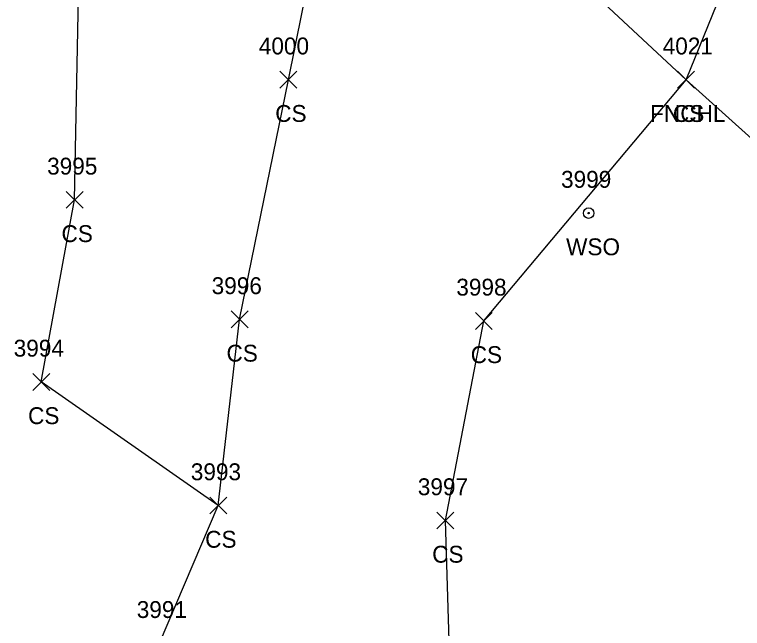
# Model space of a CAD drawing. Extents: x 49137 to 50946, y 9590 to 10709.
# Drawn here: x 49899.3 to 49985.5, y 10501.9 to 10574.6 of the extents above; entities that cross this region are included whole.
import ezdxf

# ---------------------------------------------------------------- set-up
doc = ezdxf.new("R2010")
doc.units = 0
for name, color, linetype in [('L_A', 7, 'Continuous'), ('L_I', 7, 'Continuous'), ('L_TIC', 7, 'Continuous'), ('LELB', 7, 'Continuous'), ('LFNC', 7, 'Continuous'), ('U_A', 7, 'Continuous'), ('U_I', 7, 'Continuous'), ('UWV', 7, 'Continuous')]:
    doc.layers.add(name, color=color, linetype=linetype)

msp = doc.modelspace()

# ---------------------------------------------------------------- linework, layer by layer
at = {"layer": 'L_TIC'}
for points in [[(49930.688, 10565.921), (49932.688, 10567.921)], [(49932.688, 10565.921), (49930.688, 10567.921)], [(49977.784, 10565.915), (49979.784, 10567.915)], [(49979.784, 10565.915), (49977.784, 10567.915)], [(49977.784, 10565.915), (49979.784, 10567.915)], [(49979.784, 10565.915), (49977.784, 10567.915)], [(49905.375, 10551.679), (49907.375, 10553.679)], [(49907.375, 10551.679), (49905.375, 10553.679)], [(49924.914, 10537.511), (49926.914, 10539.511)], [(49926.914, 10537.511), (49924.914, 10539.511)], [(49953.835, 10537.337), (49955.835, 10539.337)], [(49955.835, 10537.337), (49953.835, 10539.337)], [(49901.416, 10530.105), (49903.416, 10532.105)], [(49903.416, 10530.105), (49901.416, 10532.105)], [(49922.39, 10515.456), (49924.39, 10517.456)], [(49924.39, 10515.456), (49922.39, 10517.456)], [(49922.39, 10515.456), (49924.39, 10517.456)], [(49924.39, 10515.456), (49922.39, 10517.456)], [(49949.273, 10513.682), (49951.273, 10515.682)], [(49951.273, 10513.682), (49949.273, 10515.682)]]:
    msp.add_lwpolyline(points, dxfattribs=at)
at = {"layer": 'LELB'}
for points in [[(49923.39, 10516.456), (49902.416, 10531.105), (49906.375, 10552.679), (49907.277, 10598.859), (49920.121, 10622.736)], [(49949.012, 10468.446), (49916.195, 10486.119), (49916.422, 10500.13), (49923.39, 10516.456), (49925.914, 10538.511), (49931.688, 10566.921), (49939.033, 10603.327)], [(49951.21, 10484.843), (49950.273, 10514.682), (49954.835, 10538.337), (49978.784, 10566.915), (49984.016, 10579.774), (50007.672, 10594.029), (50036.301, 10599.804)]]:
    msp.add_lwpolyline(points, dxfattribs=at)
at = {"layer": 'LFNC'}
msp.add_lwpolyline([(49920.121, 10622.736), (49939.033, 10603.327), (49958.78, 10585.587), (49978.784, 10566.915), (49996.681, 10550.816)], dxfattribs=at)
at = {"layer": 'UWV'}
for radius in [0.625, 0.0833]:
    msp.add_circle((49967.242, 10551.116), radius, dxfattribs=at)

# ---------------------------------------------------------------- texts
at = {"layer": 'L_A'}
for s, p in [('CS', (49930.129, 10561.921)), ('FNCHL', (49974.532, 10561.915)), ('CS', (49977.225, 10561.915)), ('CS', (49904.816, 10547.679)), ('CS', (49924.355, 10533.511)), ('CS', (49953.276, 10533.337)), ('CS', (49900.857, 10526.105)), ('CS', (49921.831, 10511.456)), ('CS', (49921.831, 10511.456)), ('CS', (49948.714, 10509.682))]:
    msp.add_text(s, height=2, dxfattribs=at).set_placement(p)
at = {"layer": 'L_I'}
for s, p in [('4000', (49928.184, 10569.921)), ('4021', (49976.012, 10569.915)), ('4021', (49976.012, 10569.915)), ('3995', (49903.116, 10555.679)), ('3996', (49922.599, 10541.511)), ('3998', (49951.575, 10541.337)), ('3994', (49899.156, 10534.105)), ('3993', (49920.131, 10519.456)), ('3993', (49920.131, 10519.456)), ('3997', (49947.014, 10517.682)), ('3991', (49913.729, 10503.13))]:
    msp.add_text(s, height=2, dxfattribs=at).set_placement(p)
at = {"layer": 'U_A'}
msp.add_text('WSO', height=2, dxfattribs=at).set_placement((49964.573, 10546.116))
at = {"layer": 'U_I'}
msp.add_text('3999', height=2, dxfattribs=at).set_placement((49963.975, 10554.116))

doc.saveas('drawing.dxf')
